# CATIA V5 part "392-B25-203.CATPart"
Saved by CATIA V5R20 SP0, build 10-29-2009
Part number: 392-B25-203
Definition: NONE
Nomenclature: 392-B25-203
Source: Unknown
Description: 392-B25-203
Bounding box of the stored display mesh (mm): x 0 to 203, y -12.353 to 12.353, z -12.25 to 12.064
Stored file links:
  C:\Users\Utente\Desktop\IO LAVORO\3D X SITO CF\X SITO\3D files 392B\392-B25-203.CATPart
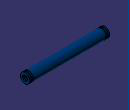
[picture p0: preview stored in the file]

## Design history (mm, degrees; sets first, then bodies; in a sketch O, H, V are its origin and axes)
Body1 "392-B25-203" (main body)
  Solid1: solid without history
